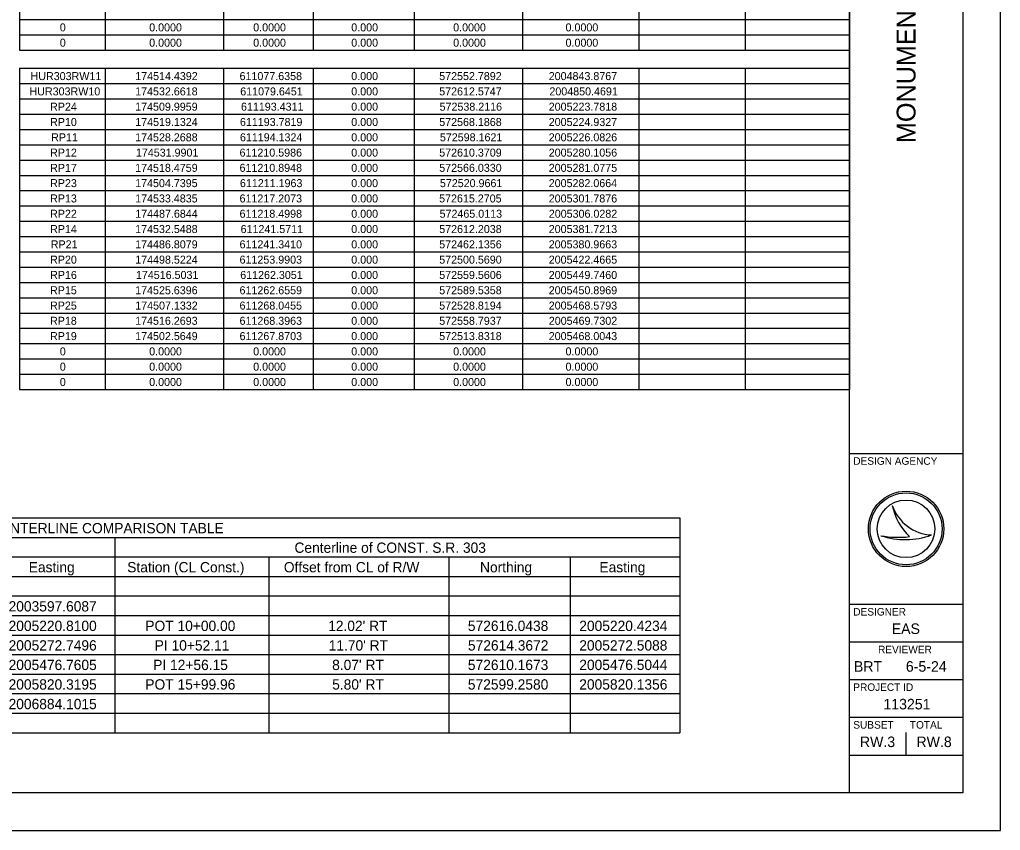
# Model space of a CAD drawing. Extents: x 0 to 34, y 0 to 22.
# Drawn here: x 21 to 34, y 0 to 10.76 of the extents above; entities that cross this region are included whole.
import ezdxf

# ---------------------------------------------------------------- set-up
doc = ezdxf.new("R2010")
doc.units = 0
for name, color, linetype in [('SH_Border', 7, 'Continuous'), ('SH_Cut_Line', 7, 'Continuous'), ('SH_Data', 7, 'Continuous'), ('SH_Text', 7, 'Continuous')]:
    doc.layers.add(name, color=color, linetype=linetype)

msp = doc.modelspace()

# ---------------------------------------------------------------- linework, layer by layer
at = {"layer": 'SH_Border'}
for p, q in [((32, 0.5), (32, 21.5)), ((32, 5), (33.5, 5)), ((32, 3), (33.5, 3)), ((32, 2.5), (33.5, 2.5)), ((32, 2), (33.5, 2)), ((32, 1.5), (33.5, 1.5)), ((32, 1), (33.5, 1))]:
    msp.add_line(p, q, dxfattribs=at)
msp.add_lwpolyline([(1.5, 21.5), (33.5, 21.5), (33.5, 0.5), (1.5, 0.5)], close=True, dxfattribs=at)
at = {"layer": 'SH_Cut_Line'}
msp.add_lwpolyline([(0, 0), (34, 0), (34, 22), (0, 22)], close=True, dxfattribs=at)
at = {"layer": 'SH_Data'}
for p, q in [((32.567, 4.31), (32.567, 4.31)), ((32.417, 3.91), (32.417, 3.91)), ((32.75, 4), (32.75, 4)), ((33.087, 3.919), (33.087, 3.919)), ((32.75, 1), (32.75, 1.3))]:
    msp.add_line(p, q, dxfattribs=at)
for radius in [0.5, 0.477, 0.477, 0.382]:
    msp.add_circle((32.75, 4), radius, dxfattribs=at)
for centre, radius, start, end in [((33.116, 4.498), 0.58, 198.9257, 198.9319), ((33.347, 4.47), 0.796, 191.6379, 191.6421), ((33.116, 4.498), 0.58, 198.9319, 267.1657), ((33.347, 4.47), 0.796, 191.6421, 226.0947), ((32.739, 4.87), 1.013, 251.4576, 290.0832), ((32.648, 5.154), 1.266, 259.4964, 259.4995), ((32.739, 4.87), 1.013, 251.4527, 251.4576), ((32.648, 5.154), 1.266, 259.4995, 276.6672)]:
    msp.add_arc(centre, radius, start, end, dxfattribs=at)
at = {"layer": 'SH_Text'}
for p, q in [((20.997, 10.958), (20.997, 10.755)), ((22.132, 10.958), (22.132, 10.755)), ((23.699, 10.958), (23.699, 10.755)), ((24.889, 10.958), (24.889, 10.755)), ((26.226, 10.958), (26.226, 10.755)), ((27.665, 10.958), (27.665, 10.755)), ((29.205, 10.958), (29.205, 10.755)), ((30.617, 10.958), (30.617, 10.755)), ((32, 10.958), (32, 10.755)), ((20.997, 10.755), (22.132, 10.755)), ((20.997, 10.755), (20.997, 10.35)), ((22.132, 10.755), (32, 10.755)), ((22.132, 10.755), (22.132, 10.35)), ((23.699, 10.755), (23.699, 10.35)), ((24.889, 10.755), (24.889, 10.35)), ((26.226, 10.755), (26.226, 10.35)), ((27.665, 10.755), (27.665, 10.35)), ((29.205, 10.755), (29.205, 10.35)), ((30.617, 10.755), (30.617, 10.35)), ((32, 10.755), (32, 5.849)), ((20.997, 10.552), (22.132, 10.552)), ((22.132, 10.552), (32, 10.552)), ((20.997, 10.35), (22.132, 10.35)), ((22.132, 10.35), (32, 10.35)), ((20.997, 10.11), (22.132, 10.11)), ((20.997, 10.11), (20.997, 5.849)), ((22.132, 10.11), (32, 10.11)), ((22.132, 10.11), (22.132, 5.849)), ((23.699, 10.11), (23.699, 5.849)), ((24.889, 10.11), (24.889, 5.849)), ((26.226, 10.11), (26.226, 5.849)), ((27.665, 10.11), (27.665, 5.849)), ((29.205, 10.11), (29.205, 5.849)), ((30.617, 10.11), (30.617, 5.849)), ((20.997, 9.907), (22.132, 9.907)), ((22.132, 9.907), (32, 9.907)), ((20.997, 9.704), (22.132, 9.704)), ((22.132, 9.704), (32, 9.704)), ((20.997, 9.501), (22.132, 9.501)), ((22.132, 9.501), (32, 9.501)), ((20.997, 9.298), (22.132, 9.298)), ((22.132, 9.298), (32, 9.298)), ((20.997, 9.095), (22.132, 9.095)), ((22.132, 9.095), (32, 9.095)), ((20.997, 8.892), (22.132, 8.892)), ((22.132, 8.892), (32, 8.892)), ((20.997, 8.689), (22.132, 8.689)), ((22.132, 8.689), (32, 8.689)), ((20.997, 8.487), (22.132, 8.487)), ((22.132, 8.487), (32, 8.487)), ((20.997, 8.284), (22.132, 8.284)), ((22.132, 8.284), (32, 8.284)), ((20.997, 8.081), (22.132, 8.081)), ((22.132, 8.081), (32, 8.081)), ((20.997, 7.878), (22.132, 7.878)), ((22.132, 7.878), (32, 7.878)), ((20.997, 7.675), (22.132, 7.675)), ((22.132, 7.675), (32, 7.675)), ((20.997, 7.472), (22.132, 7.472)), ((22.132, 7.472), (32, 7.472)), ((20.997, 7.269), (22.132, 7.269)), ((22.132, 7.269), (32, 7.269)), ((20.997, 7.066), (22.132, 7.066)), ((22.132, 7.066), (32, 7.066)), ((20.997, 6.863), (22.132, 6.863)), ((22.132, 6.863), (32, 6.863)), ((20.997, 6.66), (22.132, 6.66)), ((22.132, 6.66), (32, 6.66)), ((20.997, 6.458), (22.132, 6.458)), ((22.132, 6.458), (32, 6.458)), ((20.997, 6.255), (22.132, 6.255)), ((22.132, 6.255), (32, 6.255)), ((20.997, 6.052), (22.132, 6.052)), ((22.132, 6.052), (32, 6.052)), ((20.997, 5.849), (22.132, 5.849)), ((22.132, 5.849), (32, 5.849)), ((20.653, 4.146), (26.689, 4.146)), ((26.689, 4.146), (28.297, 4.146)), ((28.297, 4.146), (29.749, 4.146)), ((29.749, 4.146), (29.749, 3.369)), ((20.653, 3.887), (26.689, 3.887)), ((22.261, 3.887), (22.261, 3.369)), ((26.689, 3.887), (28.297, 3.887)), ((28.297, 3.887), (29.749, 3.887)), ((20.653, 3.628), (26.689, 3.628)), ((24.301, 3.628), (24.301, 3.369)), ((26.689, 3.628), (28.297, 3.628)), ((26.689, 3.628), (26.689, 3.369)), ((28.297, 3.628), (29.749, 3.628)), ((28.297, 3.628), (28.297, 3.369)), ((20.653, 3.369), (26.689, 3.369)), ((22.261, 3.369), (22.261, 2.591)), ((24.301, 3.369), (24.301, 2.591)), ((26.689, 3.369), (28.297, 3.369)), ((26.689, 3.369), (26.689, 2.591)), ((28.297, 3.369), (29.749, 3.369)), ((28.297, 3.369), (28.297, 2.591)), ((29.749, 3.369), (29.749, 2.591)), ((20.653, 3.11), (26.689, 3.11)), ((26.689, 3.11), (28.297, 3.11)), ((28.297, 3.11), (29.749, 3.11)), ((20.653, 2.85), (26.689, 2.85)), ((26.689, 2.85), (28.297, 2.85)), ((28.297, 2.85), (29.749, 2.85)), ((20.653, 2.591), (26.689, 2.591)), ((22.261, 2.591), (22.261, 1.295)), ((24.301, 2.591), (24.301, 1.295)), ((26.689, 2.591), (28.297, 2.591)), ((26.689, 2.591), (26.689, 1.295)), ((28.297, 2.591), (29.749, 2.591)), ((28.297, 2.591), (28.297, 1.295)), ((29.749, 2.591), (29.749, 1.295)), ((20.653, 2.332), (26.689, 2.332)), ((26.689, 2.332), (28.297, 2.332)), ((28.297, 2.332), (29.749, 2.332)), ((20.653, 2.073), (26.689, 2.073)), ((26.689, 2.073), (28.297, 2.073)), ((28.297, 2.073), (29.749, 2.073)), ((20.653, 1.814), (26.689, 1.814)), ((26.689, 1.814), (28.297, 1.814)), ((28.297, 1.814), (29.749, 1.814)), ((20.653, 1.554), (26.689, 1.554)), ((26.689, 1.554), (28.297, 1.554)), ((28.297, 1.554), (29.749, 1.554)), ((20.653, 1.295), (26.689, 1.295)), ((26.689, 1.295), (28.297, 1.295)), ((28.297, 1.295), (29.749, 1.295))]:
    msp.add_line(p, q, dxfattribs=at)

# ---------------------------------------------------------------- texts
at = {"layer": 'SH_Data'}
msp.add_text('MONUMENT TABLE - HUR-303-2.42', height=0.25, rotation=90, dxfattribs=at).set_placement((32.875, 9.117))
for s, height, p in [('DESIGN AGENCY', 0.1, (32.05, 4.85)), ('DESIGNER', 0.1, (32.05, 2.85)), ('EAS', 0.14, (32.559, 2.605)), ('REVIEWER', 0.1, (32.378, 2.35)), ('BRT', 0.14, (32.058, 2.105)), ('6-5-24', 0.14, (32.747, 2.105)), ('PROJECT ID', 0.1, (32.05, 1.85)), ('113251', 0.14, (32.449, 1.605)), ('SUBSET', 0.1, (32.05, 1.35)), ('TOTAL', 0.1, (32.8, 1.35)), ('RW.3', 0.14, (32.137, 1.105)), ('RW.8', 0.14, (32.887, 1.105))]:
    msp.add_text(s, height=height, dxfattribs=at).set_placement(p)
at = {"layer": 'SH_Text'}
for s, height, p in [('0', 0.106, (21.53, 10.599)), ('0.0000', 0.1061, (22.715, 10.599)), ('0.0000', 0.1061, (24.094, 10.599)), ('0.000', 0.1061, (25.394, 10.599)), ('0.0000', 0.1061, (26.745, 10.599)), ('0.0000', 0.1061, (28.235, 10.599)), ('0', 0.106, (21.53, 10.396)), ('0.0000', 0.1061, (22.715, 10.396)), ('0.0000', 0.1061, (24.094, 10.396)), ('0.000', 0.1061, (25.394, 10.396)), ('0.0000', 0.1061, (26.745, 10.396)), ('0.0000', 0.1061, (28.235, 10.396)), ('HUR303RW11', 0.1061, (21.142, 9.953)), ('174514.4392', 0.10606, (22.53, 9.953)), ('611077.6358', 0.10606, (23.913, 9.953)), ('0.000', 0.1061, (25.394, 9.953)), ('572552.7892', 0.10606, (26.56, 9.953)), ('2004843.8767', 0.10606, (28.012, 9.953)), ('HUR303RW10', 0.1061, (21.128, 9.75)), ('174532.6618', 0.10606, (22.529, 9.75)), ('611079.6451', 0.10606, (23.922, 9.75)), ('0.000', 0.1061, (25.394, 9.75)), ('572612.5747', 0.10606, (26.56, 9.75)), ('2004850.4691', 0.10606, (28.021, 9.75)), ('RP24', 0.1061, (21.401, 9.547)), ('174509.9959', 0.10606, (22.529, 9.547)), ('611193.4311', 0.10606, (23.932, 9.547)), ('0.000', 0.1061, (25.394, 9.547)), ('572538.2116', 0.10606, (26.565, 9.547)), ('2005223.7818', 0.10606, (28.012, 9.547)), ('RP10', 0.1061, (21.401, 9.344)), ('174519.1324', 0.10606, (22.53, 9.344)), ('611193.7819', 0.10606, (23.918, 9.344)), ('0.000', 0.1061, (25.394, 9.344)), ('572568.1868', 0.10606, (26.56, 9.344)), ('2005224.9327', 0.10606, (28.012, 9.344)), ('RP11', 0.1061, (21.415, 9.141)), ('174528.2688', 0.10606, (22.529, 9.141)), ('611194.1324', 0.10606, (23.918, 9.141)), ('0.000', 0.1061, (25.394, 9.141)), ('572598.1621', 0.10606, (26.569, 9.141)), ('2005226.0826', 0.10606, (28.012, 9.141)), ('RP12', 0.1061, (21.401, 8.938)), ('174531.9901', 0.10606, (22.539, 8.938)), ('611210.5986', 0.10606, (23.913, 8.938)), ('0.000', 0.1061, (25.394, 8.938)), ('572610.3709', 0.10606, (26.56, 8.938)), ('2005280.1056', 0.10606, (28.012, 8.938)), ('174518.4759', 0.10606, (22.529, 8.736)), ('611210.8948', 0.10606, (23.913, 8.736)), ('0.000', 0.1061, (25.394, 8.736)), ('572566.0330', 0.10606, (26.56, 8.736)), ('2005281.0775', 0.10606, (28.012, 8.736)), ('RP17', 0.1061, (21.401, 8.736)), ('RP23', 0.1061, (21.401, 8.533)), ('174504.7395', 0.10606, (22.529, 8.533)), ('611211.1963', 0.10606, (23.918, 8.533)), ('0.000', 0.1061, (25.394, 8.533)), ('572520.9661', 0.10606, (26.569, 8.533)), ('2005282.0664', 0.10606, (28.012, 8.533)), ('RP13', 0.1061, (21.401, 8.33)), ('174533.4835', 0.10606, (22.529, 8.33)), ('611217.2073', 0.10606, (23.913, 8.33)), ('0.000', 0.1061, (25.394, 8.33)), ('572615.2705', 0.10606, (26.559, 8.33)), ('2005301.7876', 0.10606, (28.012, 8.33)), ('RP22', 0.1061, (21.401, 8.127)), ('174487.6844', 0.10606, (22.53, 8.127)), ('611218.4998', 0.10606, (23.913, 8.127)), ('0.000', 0.1061, (25.394, 8.127)), ('572465.0113', 0.10606, (26.565, 8.127)), ('2005306.0282', 0.10606, (28.013, 8.127)), ('RP14', 0.1061, (21.401, 7.924)), ('174532.5488', 0.10606, (22.529, 7.924)), ('611241.5711', 0.10606, (23.927, 7.924)), ('0.000', 0.1061, (25.394, 7.924)), ('572612.2038', 0.10606, (26.56, 7.924)), ('2005381.7213', 0.10606, (28.012, 7.924)), ('RP21', 0.1061, (21.41, 7.721)), ('174486.8079', 0.10606, (22.529, 7.721)), ('611241.3410', 0.10606, (23.913, 7.721)), ('0.000', 0.1061, (25.394, 7.721)), ('572462.1356', 0.10606, (26.56, 7.721)), ('2005380.9663', 0.10606, (28.012, 7.721)), ('RP20', 0.1061, (21.401, 7.518)), ('174498.5224', 0.10606, (22.53, 7.518)), ('611253.9903', 0.10606, (23.913, 7.518)), ('0.000', 0.1061, (25.394, 7.518)), ('572500.5690', 0.10606, (26.56, 7.518)), ('2005422.4665', 0.10606, (28.012, 7.518)), ('RP16', 0.1061, (21.401, 7.315)), ('174516.5031', 0.10606, (22.539, 7.315)), ('611262.3051', 0.10606, (23.922, 7.315)), ('0.000', 0.1061, (25.394, 7.315)), ('572559.5606', 0.10606, (26.56, 7.315)), ('2005449.7460', 0.10606, (28.012, 7.315)), ('RP15', 0.1061, (21.4, 7.112)), ('174525.6396', 0.10606, (22.529, 7.112)), ('611262.6559', 0.10606, (23.913, 7.112)), ('0.000', 0.1061, (25.394, 7.112)), ('572589.5358', 0.10606, (26.56, 7.112)), ('2005450.8969', 0.10606, (28.012, 7.112)), ('RP25', 0.1061, (21.4, 6.909)), ('174507.1332', 0.10606, (22.53, 6.909)), ('611268.0455', 0.10606, (23.913, 6.909)), ('0.000', 0.1061, (25.394, 6.909)), ('572528.8194', 0.10606, (26.56, 6.909)), ('2005468.5793', 0.10606, (28.012, 6.909)), ('RP18', 0.1061, (21.4, 6.707)), ('174516.2693', 0.10606, (22.529, 6.707)), ('611268.3963', 0.10606, (23.913, 6.707)), ('0.000', 0.1061, (25.394, 6.707)), ('572558.7937', 0.10606, (26.56, 6.707)), ('2005469.7302', 0.10606, (28.013, 6.707)), ('RP19', 0.1061, (21.4, 6.504)), ('174502.5649', 0.10606, (22.529, 6.504)), ('611267.8703', 0.10606, (23.913, 6.504)), ('0.000', 0.1061, (25.394, 6.504)), ('572513.8318', 0.10606, (26.56, 6.504)), ('2005468.0043', 0.10606, (28.012, 6.504)), ('0', 0.106, (21.53, 6.301)), ('0.0000', 0.1061, (22.715, 6.301)), ('0.0000', 0.1061, (24.094, 6.301)), ('0.000', 0.1061, (25.394, 6.301)), ('0.0000', 0.1061, (26.745, 6.301)), ('0.0000', 0.1061, (28.235, 6.301)), ('0', 0.106, (21.53, 6.098)), ('0.0000', 0.1061, (22.715, 6.098)), ('0.0000', 0.1061, (24.094, 6.098)), ('0.000', 0.1061, (25.394, 6.098)), ('0.0000', 0.1061, (26.745, 6.098)), ('0.0000', 0.1061, (28.235, 6.098)), ('0', 0.106, (21.53, 5.895)), ('0.0000', 0.1061, (22.715, 5.895)), ('0.0000', 0.1061, (24.094, 5.895)), ('0.000', 0.1061, (25.394, 5.895)), ('0.0000', 0.1061, (26.745, 5.895)), ('0.0000', 0.1061, (28.235, 5.895)), ('CENTERLINE COMPARISON TABLE', 0.13662, (20.617, 3.941)), ('Centerline of CONST. S.R. 303', 0.13662, (24.641, 3.682)), ('Easting', 0.1366, (21.118, 3.423)), ('Station (CL Const.)', 0.13662, (22.424, 3.423)), ('Offset from CL of R/W', 0.13662, (24.5, 3.423)), ('Northing', 0.1366, (27.101, 3.423)), ('Easting', 0.1366, (28.684, 3.423)), ('2003597.6087', 0.13662, (20.851, 2.904)), ('2005220.8100', 0.13662, (20.851, 2.645)), ('POT 10+00.00', 0.13662, (22.664, 2.645)), ("12.02' RT", 0.1366, (25.088, 2.645)), ('572616.0438', 0.13662, (26.94, 2.645)), ('2005220.4234', 0.13662, (28.417, 2.645)), ('2005272.7496', 0.13662, (20.851, 2.386)), ('PI 10+52.11', 0.13662, (22.788, 2.386)), ("11.70' RT", 0.1366, (25.095, 2.386)), ('572614.3672', 0.13662, (26.941, 2.386)), ('2005272.5088', 0.13662, (28.417, 2.386)), ('2005476.7605', 0.13662, (20.851, 2.127)), ('PI 12+56.15', 0.13662, (22.768, 2.127)), ("8.07' RT", 0.1366, (25.141, 2.127)), ('572610.1673', 0.13662, (26.94, 2.127)), ('2005476.5044', 0.13662, (28.417, 2.127)), ('2005820.3195', 0.13662, (20.851, 1.868)), ('POT 15+99.96', 0.13662, (22.664, 1.868)), ("5.80' RT", 0.1366, (25.141, 1.868)), ('572599.2580', 0.13662, (26.94, 1.868)), ('2005820.1356', 0.13662, (28.417, 1.868)), ('2006884.1015', 0.13662, (20.851, 1.608))]:
    msp.add_text(s, height=height, dxfattribs=at).set_placement(p)

doc.saveas('drawing.dxf')
